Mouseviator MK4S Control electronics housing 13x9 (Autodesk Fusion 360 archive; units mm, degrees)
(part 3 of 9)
sketch "Side locks" plane through (100.9644, 0, 0) normal (1, 0, 0) x axis (0, 1, 0)
  line L1 (61.9172, 74.95) -> (61.9172, 5.05)
  line L2 (-67.9414, 74.95) -> (61.9172, 74.95)
  line L3 (-67.9414, 5.05) -> (-67.9414, 74.95)
  line L4 (61.9172, 5.05) -> (-67.9414, 5.05)
  line L5 (-3.0121, 22.271) -> (-3.0121, 127.629)
  line L6 (25.9775, 40) -> (-161.8603, 40)
  line L7 (-67.9414, 64.95) -> (-67.9414, 74.95)
  line L8 (-61.9414, 74.95) -> (-67.9414, 74.95)
  line L9 (-61.9414, 59.95) -> (-61.9414, 74.95)
  line L10 (-67.9414, 64.95) -> (-61.9414, 59.95)
  line L11 (-67.9471, 64.9636) -> (-73.8914, 60.0101)
  line L12 (-73.8914, 60.0101) -> (-73.8914, 74.9101)
  line L13 (-67.9414, 64.9636) -> (-67.9471, 64.9636)
  line L14 (-67.9414, 74.9101) -> (-73.8914, 74.9101)
  line L15 (-67.9414, 5.0899) -> (-73.8914, 5.0899)
  line L16 (-73.8914, 19.9899) -> (-73.8914, 5.0899)
  line L17 (-67.9471, 15.0364) -> (-73.8914, 19.9899)
  line L18 (-67.9414, 15.0364) -> (-67.9471, 15.0364)
  line L19 (-67.9414, 15.05) -> (-67.9414, 5.05)
  line L20 (-61.9414, 5.05) -> (-67.9414, 5.05)
  line L21 (-61.9414, 20.05) -> (-61.9414, 5.05)
  line L22 (-67.9414, 15.05) -> (-61.9414, 20.05)
  line L23 (61.9172, 64.95) -> (61.9172, 74.95)
  line L24 (55.9172, 74.95) -> (61.9172, 74.95)
  line L25 (55.9172, 59.95) -> (55.9172, 74.95)
  line L26 (61.9172, 64.95) -> (55.9172, 59.95)
  line L27 (61.9172, 74.9101) -> (67.8672, 74.9101)
  line L28 (67.8672, 60.0101) -> (67.8672, 74.9101)
  line L29 (61.9172, 64.9636) -> (61.9229, 64.9636)
  line L30 (61.9229, 64.9636) -> (67.8672, 60.0101)
  line L31 (61.9172, 5.0899) -> (67.8672, 5.0899)
  line L32 (67.8672, 19.9899) -> (67.8672, 5.0899)
  line L33 (61.9172, 15.0364) -> (61.9229, 15.0364)
  line L34 (61.9229, 15.0364) -> (67.8672, 19.9899)
  line L35 (61.9172, 15.05) -> (61.9172, 5.05)
  line L36 (55.9172, 5.05) -> (61.9172, 5.05)
  line L37 (55.9172, 20.05) -> (55.9172, 5.05)
  line L38 (61.9172, 15.05) -> (55.9172, 20.05)
  point P17 (-67.9414, 64.9636)
  point P18 (-67.9414, 74.9101)
  point P10 (-67.9414, 74.95)
  point P24 (-67.9414, 5.05)
  point P11 (-67.9414, 64.95)
  point P25 (-67.9414, 15.05)
  point P12 (-61.9414, 74.95)
  point P26 (-61.9414, 5.05)
  point P13 (-61.9414, 59.95)
  point P27 (-61.9414, 20.05)
  point P14 (-67.9471, 64.9636)
  point P22 (-67.9471, 15.0364)
  point P15 (-73.8914, 60.0101)
  point P21 (-73.8914, 19.9899)
  point P16 (-73.8914, 74.9101)
  point P19 (-73.8914, 5.0899)
  point P23 (-67.9414, 15.0364)
  point P20 (-67.9414, 5.0899)
  point P28 (61.9172, 74.95)
  point P29 (61.9172, 64.95)
  point P30 (55.9172, 74.95)
  point P31 (55.9172, 59.95)
  point P35 (61.9229, 64.9636)
  point P34 (67.8672, 60.0101)
  point P32 (67.8672, 74.9101)
  point P36 (61.9172, 64.9636)
  point P33 (61.9172, 74.9101)
  point P37 (67.8672, 5.0899)
  point P38 (61.9172, 5.0899)
  point P39 (67.8672, 19.9899)
  point P40 (61.9229, 15.0364)
  point P41 (61.9172, 15.0364)
  point P42 (61.9172, 5.05)
  point P43 (61.9172, 15.05)
  point P44 (55.9172, 5.05)
  point P45 (55.9172, 20.05)
  vertical L5
  perpendicular L1 L6
  coincident L7 P17
  horizontal L14
  coincident L3 P18
  symmetric L6 P10 P24
  symmetric L6 P11 P25
  symmetric L6 P12 P26
  symmetric L6 P13 P27
  symmetric L6 P14 P22
  symmetric L6 P15 P21
  symmetric L6 P16 P19
  symmetric L6 P17 P23
  symmetric L6 P18 P20
  midpoint L2 L5
  midpoint L3 L6
  symmetric L5 P10 P28
  symmetric L5 P11 P29
  symmetric L5 P12 P30
  symmetric L5 P13 P31
  symmetric L5 P14 P35
  symmetric L5 P15 P34
  symmetric L5 P16 P32
  symmetric L5 P17 P36
  symmetric L5 P18 P33
  symmetric L5 P19 P37
  symmetric L5 P20 P38
  symmetric L5 P21 P39
  symmetric L5 P22 P40
  symmetric L5 P23 P41
  symmetric L5 P24 P42
  symmetric L5 P25 P43
  symmetric L5 P26 P44
  symmetric L5 P27 P45
  dimension "d315" distance P12 P13 = 15 (= "join_width2")
  dimension "d316" distance P10 P11 = 10 (= "join_width1")
  dimension "d317" distance P10 P12 = 6 (= "join_depth * 2")
  dimension "d320" distance P16 P18 = 5.95 (= "join_depth * 2 - wall_clearance")
  dimension "d321" distance P15 P16 = 14.9 (= "join_width2 - 2 * wall_clearance")
sketch "wall_base" plane through (0, 0, 5) normal (0, 0, 1) x axis (-1, 0, 0)
  line L1 (-98.9644, -53.9879) -> (-98.9644, -59.9879)
  line L2 (-92.9644, -53.9879) -> (-98.9644, -53.9879)
  line L3 (-92.9644, -59.9879) -> (-92.9644, -53.9879)
  line L4 (-98.9644, -59.9879) -> (-92.9644, -59.9879)
  line L5 (-12.9644, 60.0121) -> (-12.9644, 66.0121)
  line L6 (-18.9644, 60.0121) -> (-12.9644, 60.0121)
  line L7 (-18.9644, 66.0121) -> (-18.9644, 60.0121)
  line L8 (-12.9644, 66.0121) -> (-18.9644, 66.0121)
  line L9 (-45.9644, -51.9879) -> (-20.9644, -51.9879)
  line L10 (-40.9644, -54.9879) -> (-45.9644, -51.9879)
  line L11 (-70.9644, -54.9879) -> (-40.9644, -54.9879)
  line L12 (-65.9644, -51.9879) -> (-70.9644, -54.9879)
  line L13 (-90.9644, -51.9879) -> (-65.9644, -51.9879)
  line L14 (-90.9644, -6.9879) -> (-90.9644, -51.9879)
  line L15 (-93.9644, -11.9879) -> (-90.9644, -6.9879)
  line L16 (-93.9644, 18.0121) -> (-93.9644, -11.9879)
  line L17 (-90.9644, 13.0121) -> (-93.9644, 18.0121)
  line L18 (-90.9644, 58.0121) -> (-90.9644, 13.0121)
  line L19 (-65.9644, 58.0121) -> (-90.9644, 58.0121)
  line L20 (-70.9644, 61.0121) -> (-65.9644, 58.0121)
  line L21 (-40.9644, 61.0121) -> (-70.9644, 61.0121)
  line L22 (-45.9644, 58.0121) -> (-40.9644, 61.0121)
  line L23 (-20.9644, 58.0121) -> (-45.9644, 58.0121)
  line L24 (-20.9644, 13.0121) -> (-20.9644, 58.0121)
  line L25 (-17.9644, 18.0121) -> (-20.9644, 13.0121)
  line L26 (-17.9644, -11.9879) -> (-17.9644, 18.0121)
  line L27 (-20.9644, -6.9879) -> (-17.9644, -11.9879)
  line L28 (-20.9644, -51.9879) -> (-20.9644, -6.9879)
  line L29 (-12.9644, -53.9879) -> (-18.9644, -53.9879)
  line L30 (-12.9644, -59.9879) -> (-12.9644, -53.9879)
  line L31 (-18.9644, -59.9879) -> (-12.9644, -59.9879)
  line L32 (-18.9644, -53.9879) -> (-18.9644, -59.9879)
  line L33 (-98.9644, 60.0121) -> (-92.9644, 60.0121)
  line L34 (-98.9644, 66.0121) -> (-98.9644, 60.0121)
  line L35 (-92.9644, 66.0121) -> (-98.9644, 66.0121)
  line L36 (-92.9644, 60.0121) -> (-92.9644, 66.0121)
  line L37 (-10.9644, -6.9879) -> (-10.9644, -61.9879)
  line L38 (-13.9644, -11.9879) -> (-10.9644, -6.9879)
  line L39 (-13.9644, 18.0121) -> (-13.9644, -11.9879)
  line L40 (-10.9644, 13.0121) -> (-13.9644, 18.0121)
  line L41 (-10.9644, 68.0121) -> (-10.9644, 13.0121)
  line L42 (-45.9644, 68.0121) -> (-10.9644, 68.0121)
  line L43 (-40.9644, 65.0121) -> (-45.9644, 68.0121)
  line L44 (-70.9644, 65.0121) -> (-40.9644, 65.0121)
  line L45 (-65.9644, 68.0121) -> (-70.9644, 65.0121)
  line L46 (-100.9644, 68.0121) -> (-65.9644, 68.0121)
  line L47 (-100.9644, 13.0121) -> (-100.9644, 68.0121)
  line L48 (-97.9644, 18.0121) -> (-100.9644, 13.0121)
  line L49 (-97.9644, -11.9879) -> (-97.9644, 18.0121)
  line L50 (-100.9644, -6.9879) -> (-97.9644, -11.9879)
  line L51 (-100.9644, -61.9879) -> (-100.9644, -6.9879)
  line L52 (-65.9644, -61.9879) -> (-100.9644, -61.9879)
  line L53 (-70.9644, -58.9879) -> (-65.9644, -61.9879)
  line L54 (-40.9644, -58.9879) -> (-70.9644, -58.9879)
  line L55 (-45.9644, -61.9879) -> (-40.9644, -58.9879)
  line L56 (-10.9644, -61.9879) -> (-45.9644, -61.9879)
  line L57 (-100.9644, -61.9879) -> (-100.9644, 68.0121)
  line L58 (-100.9644, -61.9172) -> (-100.0144, -60.9672)
  line L59 (-100.0144, -52.9379) -> (-100.0144, -60.9672)
  line L60 (-99.0144, -52.9379) -> (-100.0144, -52.9379)
  line L61 (-99.0144, 58.9451) -> (-99.0144, -52.9379)
  line L62 (-100.0144, 58.9621) -> (-99.0144, 58.9451)
  line L63 (-100.0144, 66.9914) -> (-100.0144, 58.9621)
  line L64 (-100.9644, 67.9414) -> (-100.0144, 66.9914)
  line L65 (-99.9644, -52.9879) -> (-99.9644, -60.9879)
  line L66 (-98.9644, -52.9879) -> (-99.9644, -52.9879)
  line L67 (-98.9644, 58.9942) -> (-98.9644, -52.9879)
  line L68 (-99.9644, 59.0113) -> (-98.9644, 58.9942)
  line L69 (-99.9644, 67.0121) -> (-99.9644, 59.0113)
  line L70 (-100.9644, -61.9879) -> (-99.9644, -60.9879)
  line L71 (-100.9644, 68.0121) -> (-99.9644, 67.0121)
  circle C1 centre (-24.4644, 61.5121) radius 1.7
  circle C2 centre (-93.9644, 54.5121) radius 1.7
  circle C3 centre (-87.4644, -55.4879) radius 1.7
  circle C4 centre (-17.4644, -48.4879) radius 1.7
  circle C5 centre (-24.4644, -55.4879) radius 1.7
  circle C6 centre (-93.9644, -48.4879) radius 1.7
  circle C7 centre (-87.4644, 61.5121) radius 1.7
  circle C8 centre (-17.4644, 54.5121) radius 1.7
  point P69 (-100.9644, 68.0121)
  point P74 (-100.9644, 68.0121)
  point P68 (-100.9644, -61.9879)
  point P75 (-100.9644, -61.9879)
  point P82 (-100.9644, 67.9414)
  point P83 (-100.9644, -61.9172)
  point P90 (-100.9644, -61.9879)
  point P91 (-100.9644, 68.0121)
  point P77 (-100.0144, -52.9379)
  point P80 (-100.0144, 58.9621)
  coincident P69 P74
  coincident P68 P75
  coincident L47 P82
  coincident L51 P83
  coincident P68 P90
  parallel L58 L70
  coincident P69 P91
  dimension "d147_1" distance L57 L63 = 0.95 (= "side_wall_thick1")
  dimension "d148_1" distance L57 L61 = 1.95 (= "side_wall_thick2")
  dimension "d151_1" distance L57 L59 = 0.95 (= "side_wall_thick1")
  dimension "d157_1" distance L64 L71 = 0.05 (= "wall_clearance")
  dimension "d158_1" distance L58 L70 = 0.05 (= "wall_clearance")
  dimension "wall_rorner_angle_1" angle L46 L71 = 45
  dimension "d165_1" angle L52 L70 = 45 (= "wall_rorner_angle_1")
  dimension "d170_1" distance P75 P77 = 9.05
  dimension "d175_1" distance P74 P80 = 9.05 (= "side_wall_col_length")
extrude "Extrude1" new body sketch "wall_base" profile of L47 L48 L50 L51 L57 L58 L59 L62 L61 L60 L63 L64 blind 69.9 (= "column_height - ( 2 * wall_clearance )") named "d128_1" from offset 0.05 (= "wall_clearance") named "d127_1" bodies "side cover"
sketch "Sketch3" plane through (100.9644, 0, 0) normal (1, 0, 0) x axis (0, 1, 0)
  line L1 (61.9172, 5.05) -> (-67.9414, 5.05)
  line L2 (61.9172, 74.95) -> (61.9172, 5.05)
  line L3 (-67.9414, 74.95) -> (61.9172, 74.95)
  line L4 (-67.9414, 5.05) -> (-67.9414, 74.95)
  line L5 (61.9172, 74.95) -> (-67.9414, 74.95)
  line L6 (61.9172, 74.95) -> (61.9172, 5.05)
  line L7 (61.9172, 5.05) -> (-67.9414, 5.05)
  line L8 (-67.9414, 74.95) -> (-67.9414, 5.05)
  line L9 (-57.9414, 64.95) -> (51.9172, 64.95)
  line L10 (-57.9414, 15.05) -> (-57.9414, 64.95)
  line L11 (51.9172, 15.05) -> (-57.9414, 15.05)
  line L12 (51.9172, 64.95) -> (51.9172, 15.05)
  circle C1 centre (-62.995, 60) radius 1.7
  circle C2 centre (-62.995, 20) radius 1.7
  circle C3 centre (56.9879, 60) radius 1.7
  circle C4 centre (56.9879, 20) radius 1.7
sketch "Side locks" plane through (100.9644, 0, 0) normal (1, 0, 0) x axis (0, 1, 0)
  line L1 (61.9172, 74.95) -> (61.9172, 5.05)
  line L2 (-67.9414, 74.95) -> (61.9172, 74.95)
  line L3 (-67.9414, 5.05) -> (-67.9414, 74.95)
  line L4 (61.9172, 5.05) -> (-67.9414, 5.05)
  line L5 (-3.0121, 22.271) -> (-3.0121, 127.629)
  line L6 (25.9775, 40) -> (-161.8603, 40)
  line L7 (-67.9414, 64.95) -> (-67.9414, 74.95)
  line L8 (-61.9414, 74.95) -> (-67.9414, 74.95)
  line L9 (-61.9414, 59.95) -> (-61.9414, 74.95)
  line L10 (-67.9414, 64.95) -> (-61.9414, 59.95)
  line L11 (-67.9471, 64.9636) -> (-73.8914, 60.0101)
  line L12 (-73.8914, 60.0101) -> (-73.8914, 74.9101)
  line L13 (-67.9414, 64.9636) -> (-67.9471, 64.9636)
  line L14 (-67.9414, 74.9101) -> (-73.8914, 74.9101)
  line L15 (-67.9414, 5.0899) -> (-73.8914, 5.0899)
  line L16 (-73.8914, 19.9899) -> (-73.8914, 5.0899)
  line L17 (-67.9471, 15.0364) -> (-73.8914, 19.9899)
  line L18 (-67.9414, 15.0364) -> (-67.9471, 15.0364)
  line L19 (-67.9414, 15.05) -> (-67.9414, 5.05)
  line L20 (-61.9414, 5.05) -> (-67.9414, 5.05)
  line L21 (-61.9414, 20.05) -> (-61.9414, 5.05)
  line L22 (-67.9414, 15.05) -> (-61.9414, 20.05)
  line L23 (61.9172, 64.95) -> (61.9172, 74.95)
  line L24 (55.9172, 74.95) -> (61.9172, 74.95)
  line L25 (55.9172, 59.95) -> (55.9172, 74.95)
  line L26 (61.9172, 64.95) -> (55.9172, 59.95)
  line L27 (61.9172, 74.9101) -> (67.8672, 74.9101)
  line L28 (67.8672, 60.0101) -> (67.8672, 74.9101)
  line L29 (61.9172, 64.9636) -> (61.9229, 64.9636)
  line L30 (61.9229, 64.9636) -> (67.8672, 60.0101)
  line L31 (61.9172, 5.0899) -> (67.8672, 5.0899)
  line L32 (67.8672, 19.9899) -> (67.8672, 5.0899)
  line L33 (61.9172, 15.0364) -> (61.9229, 15.0364)
  line L34 (61.9229, 15.0364) -> (67.8672, 19.9899)
  line L35 (61.9172, 15.05) -> (61.9172, 5.05)
  line L36 (55.9172, 5.05) -> (61.9172, 5.05)
  line L37 (55.9172, 20.05) -> (55.9172, 5.05)
  line L38 (61.9172, 15.05) -> (55.9172, 20.05)
  point P17 (-67.9414, 64.9636)
  point P18 (-67.9414, 74.9101)
  point P10 (-67.9414, 74.95)
  point P24 (-67.9414, 5.05)
  point P11 (-67.9414, 64.95)
  point P25 (-67.9414, 15.05)
  point P12 (-61.9414, 74.95)
  point P26 (-61.9414, 5.05)
  point P13 (-61.9414, 59.95)
  point P27 (-61.9414, 20.05)
  point P14 (-67.9471, 64.9636)
  point P22 (-67.9471, 15.0364)
  point P15 (-73.8914, 60.0101)
  point P21 (-73.8914, 19.9899)
  point P16 (-73.8914, 74.9101)
  point P19 (-73.8914, 5.0899)
  point P23 (-67.9414, 15.0364)
  point P20 (-67.9414, 5.0899)
  point P28 (61.9172, 74.95)
  point P29 (61.9172, 64.95)
  point P30 (55.9172, 74.95)
  point P31 (55.9172, 59.95)
  point P35 (61.9229, 64.9636)
  point P34 (67.8672, 60.0101)
  point P32 (67.8672, 74.9101)
  point P36 (61.9172, 64.9636)
  point P33 (61.9172, 74.9101)
  point P37 (67.8672, 5.0899)
  point P38 (61.9172, 5.0899)
  point P39 (67.8672, 19.9899)
  point P40 (61.9229, 15.0364)
  point P41 (61.9172, 15.0364)
  point P42 (61.9172, 5.05)
  point P43 (61.9172, 15.05)
  point P44 (55.9172, 5.05)
  point P45 (55.9172, 20.05)
  vertical L5
  perpendicular L1 L6
  coincident L7 P17
  horizontal L14
  coincident L3 P18
  symmetric L6 P10 P24
  symmetric L6 P11 P25
  symmetric L6 P12 P26
  symmetric L6 P13 P27
  symmetric L6 P14 P22
  symmetric L6 P15 P21
  symmetric L6 P16 P19
  symmetric L6 P17 P23
  symmetric L6 P18 P20
  midpoint L2 L5
  midpoint L3 L6
  symmetric L5 P10 P28
  symmetric L5 P11 P29
  symmetric L5 P12 P30
  symmetric L5 P13 P31
  symmetric L5 P14 P35
  symmetric L5 P15 P34
  symmetric L5 P16 P32
  symmetric L5 P17 P36
  symmetric L5 P18 P33
  symmetric L5 P19 P37
  symmetric L5 P20 P38
  symmetric L5 P21 P39
  symmetric L5 P22 P40
  symmetric L5 P23 P41
  symmetric L5 P24 P42
  symmetric L5 P25 P43
  symmetric L5 P26 P44
  symmetric L5 P27 P45
  dimension "d315_1" distance P12 P13 = 15 (= "join_width2")
  dimension "d316_1" distance P10 P11 = 10 (= "join_width1")
  dimension "d317_1" distance P10 P12 = 6 (= "join_depth * 2")
  dimension "d320_1" distance P16 P18 = 5.95 (= "join_depth * 2 - wall_clearance")
  dimension "d321_1" distance P15 P16 = 14.9 (= "join_width2 - 2 * wall_clearance")
position "Position9"
extrude "Extrude3" cut sketch "Side locks" profile of L1 L2 L3 L4 L7 L8 L9 L10 L19 L20 L21 L22 L23 L24 L25 L26 L35 L36 L37 L38 against normal blind 5
sketch "wall_base" plane through (0, 0, 5) normal (0, 0, 1) x axis (-1, 0, 0)
  line L1 (-98.9644, -53.9879) -> (-98.9644, -59.9879)
  line L2 (-92.9644, -53.9879) -> (-98.9644, -53.9879)
  line L3 (-92.9644, -59.9879) -> (-92.9644, -53.9879)
  line L4 (-98.9644, -59.9879) -> (-92.9644, -59.9879)
  line L5 (-12.9644, 60.0121) -> (-12.9644, 66.0121)
  line L6 (-18.9644, 60.0121) -> (-12.9644, 60.0121)
  line L7 (-18.9644, 66.0121) -> (-18.9644, 60.0121)
  line L8 (-12.9644, 66.0121) -> (-18.9644, 66.0121)
  line L9 (-45.9644, -51.9879) -> (-20.9644, -51.9879)
  line L10 (-40.9644, -54.9879) -> (-45.9644, -51.9879)
  line L11 (-70.9644, -54.9879) -> (-40.9644, -54.9879)
  line L12 (-65.9644, -51.9879) -> (-70.9644, -54.9879)
  line L13 (-90.9644, -51.9879) -> (-65.9644, -51.9879)
  line L14 (-90.9644, -6.9879) -> (-90.9644, -51.9879)
  line L15 (-93.9644, -11.9879) -> (-90.9644, -6.9879)
  line L16 (-93.9644, 18.0121) -> (-93.9644, -11.9879)
  line L17 (-90.9644, 13.0121) -> (-93.9644, 18.0121)
  line L18 (-90.9644, 58.0121) -> (-90.9644, 13.0121)
  line L19 (-65.9644, 58.0121) -> (-90.9644, 58.0121)
  line L20 (-70.9644, 61.0121) -> (-65.9644, 58.0121)
  line L21 (-40.9644, 61.0121) -> (-70.9644, 61.0121)
  line L22 (-45.9644, 58.0121) -> (-40.9644, 61.0121)
  line L23 (-20.9644, 58.0121) -> (-45.9644, 58.0121)
  line L24 (-20.9644, 13.0121) -> (-20.9644, 58.0121)
  line L25 (-17.9644, 18.0121) -> (-20.9644, 13.0121)
  line L26 (-17.9644, -11.9879) -> (-17.9644, 18.0121)
  line L27 (-20.9644, -6.9879) -> (-17.9644, -11.9879)
  line L28 (-20.9644, -51.9879) -> (-20.9644, -6.9879)
  line L29 (-12.9644, -53.9879) -> (-18.9644, -53.9879)
  line L30 (-12.9644, -59.9879) -> (-12.9644, -53.9879)
  line L31 (-18.9644, -59.9879) -> (-12.9644, -59.9879)
  line L32 (-18.9644, -53.9879) -> (-18.9644, -59.9879)
  line L33 (-98.9644, 60.0121) -> (-92.9644, 60.0121)
  line L34 (-98.9644, 66.0121) -> (-98.9644, 60.0121)
  line L35 (-92.9644, 66.0121) -> (-98.9644, 66.0121)
  line L36 (-92.9644, 60.0121) -> (-92.9644, 66.0121)
  line L37 (-10.9644, -6.9879) -> (-10.9644, -61.9879)
  line L38 (-13.9644, -11.9879) -> (-10.9644, -6.9879)
  line L39 (-13.9644, 18.0121) -> (-13.9644, -11.9879)
  line L40 (-10.9644, 13.0121) -> (-13.9644, 18.0121)
  line L41 (-10.9644, 68.0121) -> (-10.9644, 13.0121)
  line L42 (-45.9644, 68.0121) -> (-10.9644, 68.0121)
  line L43 (-40.9644, 65.0121) -> (-45.9644, 68.0121)
  line L44 (-70.9644, 65.0121) -> (-40.9644, 65.0121)
  line L45 (-65.9644, 68.0121) -> (-70.9644, 65.0121)
  line L46 (-100.9644, 68.0121) -> (-65.9644, 68.0121)
  line L47 (-100.9644, 13.0121) -> (-100.9644, 68.0121)
  line L48 (-97.9644, 18.0121) -> (-100.9644, 13.0121)
  line L49 (-97.9644, -11.9879) -> (-97.9644, 18.0121)
  line L50 (-100.9644, -6.9879) -> (-97.9644, -11.9879)
  line L51 (-100.9644, -61.9879) -> (-100.9644, -6.9879)
  line L52 (-65.9644, -61.9879) -> (-100.9644, -61.9879)
  line L53 (-70.9644, -58.9879) -> (-65.9644, -61.9879)
  line L54 (-40.9644, -58.9879) -> (-70.9644, -58.9879)
  line L55 (-45.9644, -61.9879) -> (-40.9644, -58.9879)
  line L56 (-10.9644, -61.9879) -> (-45.9644, -61.9879)
  line L57 (-100.9644, -61.9879) -> (-100.9644, 68.0121)
  line L58 (-100.9644, -61.9172) -> (-100.0144, -60.9672)
  line L59 (-100.0144, -52.9379) -> (-100.0144, -60.9672)
  line L60 (-99.0144, -52.9379) -> (-100.0144, -52.9379)
  line L61 (-99.0144, 58.9451) -> (-99.0144, -52.9379)
  line L62 (-100.0144, 58.9621) -> (-99.0144, 58.9451)
  line L63 (-100.0144, 66.9914) -> (-100.0144, 58.9621)
  line L64 (-100.9644, 67.9414) -> (-100.0144, 66.9914)
  line L65 (-99.9644, -52.9879) -> (-99.9644, -60.9879)
  line L66 (-98.9644, -52.9879) -> (-99.9644, -52.9879)
  line L67 (-98.9644, 58.9942) -> (-98.9644, -52.9879)
  line L68 (-99.9644, 59.0113) -> (-98.9644, 58.9942)
  line L69 (-99.9644, 67.0121) -> (-99.9644, 59.0113)
  line L70 (-100.9644, -61.9879) -> (-99.9644, -60.9879)
  line L71 (-100.9644, 68.0121) -> (-99.9644, 67.0121)
  circle C1 centre (-24.4644, 61.5121) radius 1.7
  circle C2 centre (-93.9644, 54.5121) radius 1.7
  circle C3 centre (-87.4644, -55.4879) radius 1.7
  circle C4 centre (-17.4644, -48.4879) radius 1.7
  circle C5 centre (-24.4644, -55.4879) radius 1.7
  circle C6 centre (-93.9644, -48.4879) radius 1.7
  circle C7 centre (-87.4644, 61.5121) radius 1.7
  circle C8 centre (-17.4644, 54.5121) radius 1.7
  point P69 (-100.9644, 68.0121)
  point P74 (-100.9644, 68.0121)
  point P68 (-100.9644, -61.9879)
  point P75 (-100.9644, -61.9879)
  point P82 (-100.9644, 67.9414)
  point P83 (-100.9644, -61.9172)
  point P90 (-100.9644, -61.9879)
  point P91 (-100.9644, 68.0121)
  point P77 (-100.0144, -52.9379)
  point P80 (-100.0144, 58.9621)
  coincident P69 P74
  coincident P68 P75
  coincident L47 P82
  coincident L51 P83
  coincident P68 P90
  parallel L58 L70
  coincident P69 P91
  dimension "d147_2" distance L57 L63 = 0.95 (= "side_wall_thick1")
  dimension "d148_2" distance L57 L61 = 1.95 (= "side_wall_thick2")
  dimension "d151_2" distance L57 L59 = 0.95 (= "side_wall_thick1")
  dimension "d157_2" distance L64 L71 = 0.05 (= "wall_clearance")
  dimension "d158_2" distance L58 L70 = 0.05 (= "wall_clearance")
  dimension "wall_rorner_angle_2" angle L46 L71 = 45
  dimension "d165_2" angle L52 L70 = 45 (= "wall_rorner_angle_2")
  dimension "d170_2" distance P75 P77 = 9.05
  dimension "d175_2" distance P74 P80 = 9.05 (= "side_wall_col_length")
extrude "Extrude1" new body sketch "wall_base" profile of L47 L48 L50 L51 L57 L58 L59 L62 L61 L60 L63 L64 blind 69.9 (= "column_height - ( 2 * wall_clearance )") named "d128_2" from offset 0.05 (= "wall_clearance") named "d127_2" bodies "side cover"
sketch "Sketch3" plane through (100.9644, 0, 0) normal (1, 0, 0) x axis (0, 1, 0)
  line L1 (61.9172, 5.05) -> (-67.9414, 5.05)
  line L2 (61.9172, 74.95) -> (61.9172, 5.05)
  line L3 (-67.9414, 74.95) -> (61.9172, 74.95)
  line L4 (-67.9414, 5.05) -> (-67.9414, 74.95)
  line L5 (61.9172, 74.95) -> (-67.9414, 74.95)
  line L6 (61.9172, 74.95) -> (61.9172, 5.05)
  line L7 (61.9172, 5.05) -> (-67.9414, 5.05)
  line L8 (-67.9414, 74.95) -> (-67.9414, 5.05)
  line L9 (-57.9414, 64.95) -> (51.9172, 64.95)
  line L10 (-57.9414, 15.05) -> (-57.9414, 64.95)
  line L11 (51.9172, 15.05) -> (-57.9414, 15.05)
  line L12 (51.9172, 64.95) -> (51.9172, 15.05)
  circle C1 centre (-62.995, 60) radius 1.7
  circle C2 centre (-62.995, 20) radius 1.7
  circle C3 centre (56.9879, 60) radius 1.7
  circle C4 centre (56.9879, 20) radius 1.7
hole "Hole1" HoleDepth 4 named "d134_1" HoleDiameter 3.4 named "d135_1" TipAngle 118 named "d136_1"
sketch "Side locks" plane through (100.9644, 0, 0) normal (1, 0, 0) x axis (0, 1, 0)
  line L1 (61.9172, 74.95) -> (61.9172, 5.05)
  line L2 (-67.9414, 74.95) -> (61.9172, 74.95)
  line L3 (-67.9414, 5.05) -> (-67.9414, 74.95)
  line L4 (61.9172, 5.05) -> (-67.9414, 5.05)
  line L5 (-3.0121, 22.271) -> (-3.0121, 127.629)
  line L6 (25.9775, 40) -> (-161.8603, 40)
  line L7 (-67.9414, 64.95) -> (-67.9414, 74.95)
  line L8 (-61.9414, 74.95) -> (-67.9414, 74.95)
  line L9 (-61.9414, 59.95) -> (-61.9414, 74.95)
  line L10 (-67.9414, 64.95) -> (-61.9414, 59.95)
  line L11 (-67.9471, 64.9636) -> (-73.8914, 60.0101)
  line L12 (-73.8914, 60.0101) -> (-73.8914, 74.9101)
  line L13 (-67.9414, 64.9636) -> (-67.9471, 64.9636)
  line L14 (-67.9414, 74.9101) -> (-73.8914, 74.9101)
  line L15 (-67.9414, 5.0899) -> (-73.8914, 5.0899)
  line L16 (-73.8914, 19.9899) -> (-73.8914, 5.0899)
  line L17 (-67.9471, 15.0364) -> (-73.8914, 19.9899)
  line L18 (-67.9414, 15.0364) -> (-67.9471, 15.0364)
  line L19 (-67.9414, 15.05) -> (-67.9414, 5.05)
  line L20 (-61.9414, 5.05) -> (-67.9414, 5.05)
  line L21 (-61.9414, 20.05) -> (-61.9414, 5.05)
  line L22 (-67.9414, 15.05) -> (-61.9414, 20.05)
  line L23 (61.9172, 64.95) -> (61.9172, 74.95)
  line L24 (55.9172, 74.95) -> (61.9172, 74.95)
  line L25 (55.9172, 59.95) -> (55.9172, 74.95)
  line L26 (61.9172, 64.95) -> (55.9172, 59.95)
  line L27 (61.9172, 74.9101) -> (67.8672, 74.9101)
  line L28 (67.8672, 60.0101) -> (67.8672, 74.9101)
  line L29 (61.9172, 64.9636) -> (61.9229, 64.9636)
  line L30 (61.9229, 64.9636) -> (67.8672, 60.0101)
  line L31 (61.9172, 5.0899) -> (67.8672, 5.0899)
  line L32 (67.8672, 19.9899) -> (67.8672, 5.0899)
  line L33 (61.9172, 15.0364) -> (61.9229, 15.0364)
  line L34 (61.9229, 15.0364) -> (67.8672, 19.9899)
  line L35 (61.9172, 15.05) -> (61.9172, 5.05)
  line L36 (55.9172, 5.05) -> (61.9172, 5.05)
  line L37 (55.9172, 20.05) -> (55.9172, 5.05)
  line L38 (61.9172, 15.05) -> (55.9172, 20.05)
  point P17 (-67.9414, 64.9636)
  point P18 (-67.9414, 74.9101)
  point P10 (-67.9414, 74.95)
  point P24 (-67.9414, 5.05)
  point P11 (-67.9414, 64.95)
  point P25 (-67.9414, 15.05)
  point P12 (-61.9414, 74.95)
  point P26 (-61.9414, 5.05)
  point P13 (-61.9414, 59.95)
  point P27 (-61.9414, 20.05)
  point P14 (-67.9471, 64.9636)
  point P22 (-67.9471, 15.0364)
  point P15 (-73.8914, 60.0101)
  point P21 (-73.8914, 19.9899)
  point P16 (-73.8914, 74.9101)
  point P19 (-73.8914, 5.0899)
  point P23 (-67.9414, 15.0364)
  point P20 (-67.9414, 5.0899)
  point P28 (61.9172, 74.95)
  point P29 (61.9172, 64.95)
  point P30 (55.9172, 74.95)
  point P31 (55.9172, 59.95)
  point P35 (61.9229, 64.9636)
  point P34 (67.8672, 60.0101)
  point P32 (67.8672, 74.9101)
  point P36 (61.9172, 64.9636)
  point P33 (61.9172, 74.9101)
  point P37 (67.8672, 5.0899)
  point P38 (61.9172, 5.0899)
  point P39 (67.8672, 19.9899)
  point P40 (61.9229, 15.0364)
  point P41 (61.9172, 15.0364)
  point P42 (61.9172, 5.05)
  point P43 (61.9172, 15.05)
  point P44 (55.9172, 5.05)
  point P45 (55.9172, 20.05)
  vertical L5
  perpendicular L1 L6
  coincident L7 P17
  horizontal L14
  coincident L3 P18
  symmetric L6 P10 P24
  symmetric L6 P11 P25
  symmetric L6 P12 P26
  symmetric L6 P13 P27
  symmetric L6 P14 P22
  symmetric L6 P15 P21
  symmetric L6 P16 P19
  symmetric L6 P17 P23
  symmetric L6 P18 P20
  midpoint L2 L5
  midpoint L3 L6
  symmetric L5 P10 P28
  symmetric L5 P11 P29
  symmetric L5 P12 P30
  symmetric L5 P13 P31
  symmetric L5 P14 P35
  symmetric L5 P15 P34
  symmetric L5 P16 P32
  symmetric L5 P17 P36
  symmetric L5 P18 P33
  symmetric L5 P19 P37
  symmetric L5 P20 P38
  symmetric L5 P21 P39
  symmetric L5 P22 P40
  symmetric L5 P23 P41
  symmetric L5 P24 P42
  symmetric L5 P25 P43
  symmetric L5 P26 P44
  symmetric L5 P27 P45
  dimension "d315_2" distance P12 P13 = 15 (= "join_width2")
  dimension "d316_2" distance P10 P11 = 10 (= "join_width1")
  dimension "d317_2" distance P10 P12 = 6 (= "join_depth * 2")
  dimension "d320_2" distance P16 P18 = 5.95 (= "join_depth * 2 - wall_clearance")
  dimension "d321_2" distance P15 P16 = 14.9 (= "join_width2 - 2 * wall_clearance")
position "Position10"
extrude "Extrude3" cut sketch "Side locks" profile of L2 L3 L4 L7 L8 L9 L10 L19 L20 L21 L22 against normal blind 5
sketch "wall_base" plane through (0, 0, 5) normal (0, 0, 1) x axis (-1, 0, 0)
  line L1 (-98.9644, -53.9879) -> (-98.9644, -59.9879)
  line L2 (-92.9644, -53.9879) -> (-98.9644, -53.9879)
  line L3 (-92.9644, -59.9879) -> (-92.9644, -53.9879)
  line L4 (-98.9644, -59.9879) -> (-92.9644, -59.9879)
  line L5 (-12.9644, 60.0121) -> (-12.9644, 66.0121)
  line L6 (-18.9644, 60.0121) -> (-12.9644, 60.0121)
  line L7 (-18.9644, 66.0121) -> (-18.9644, 60.0121)
  line L8 (-12.9644, 66.0121) -> (-18.9644, 66.0121)
  line L9 (-45.9644, -51.9879) -> (-20.9644, -51.9879)
  line L10 (-40.9644, -54.9879) -> (-45.9644, -51.9879)
  line L11 (-70.9644, -54.9879) -> (-40.9644, -54.9879)
  line L12 (-65.9644, -51.9879) -> (-70.9644, -54.9879)
  line L13 (-90.9644, -51.9879) -> (-65.9644, -51.9879)
  line L14 (-90.9644, -6.9879) -> (-90.9644, -51.9879)
  line L15 (-93.9644, -11.9879) -> (-90.9644, -6.9879)
  line L16 (-93.9644, 18.0121) -> (-93.9644, -11.9879)
  line L17 (-90.9644, 13.0121) -> (-93.9644, 18.0121)
  line L18 (-90.9644, 58.0121) -> (-90.9644, 13.0121)
  line L19 (-65.9644, 58.0121) -> (-90.9644, 58.0121)
  line L20 (-70.9644, 61.0121) -> (-65.9644, 58.0121)
  line L21 (-40.9644, 61.0121) -> (-70.9644, 61.0121)
  line L22 (-45.9644, 58.0121) -> (-40.9644, 61.0121)
  line L23 (-20.9644, 58.0121) -> (-45.9644, 58.0121)
  line L24 (-20.9644, 13.0121) -> (-20.9644, 58.0121)
  line L25 (-17.9644, 18.0121) -> (-20.9644, 13.0121)
  line L26 (-17.9644, -11.9879) -> (-17.9644, 18.0121)
  line L27 (-20.9644, -6.9879) -> (-17.9644, -11.9879)
  line L28 (-20.9644, -51.9879) -> (-20.9644, -6.9879)
  line L29 (-12.9644, -53.9879) -> (-18.9644, -53.9879)
  line L30 (-12.9644, -59.9879) -> (-12.9644, -53.9879)
  line L31 (-18.9644, -59.9879) -> (-12.9644, -59.9879)
  line L32 (-18.9644, -53.9879) -> (-18.9644, -59.9879)
  line L33 (-98.9644, 60.0121) -> (-92.9644, 60.0121)
  line L34 (-98.9644, 66.0121) -> (-98.9644, 60.0121)
  line L35 (-92.9644, 66.0121) -> (-98.9644, 66.0121)
  line L36 (-92.9644, 60.0121) -> (-92.9644, 66.0121)
  line L37 (-10.9644, -6.9879) -> (-10.9644, -61.9879)
  line L38 (-13.9644, -11.9879) -> (-10.9644, -6.9879)
  line L39 (-13.9644, 18.0121) -> (-13.9644, -11.9879)
  line L40 (-10.9644, 13.0121) -> (-13.9644, 18.0121)
  line L41 (-10.9644, 68.0121) -> (-10.9644, 13.0121)
  line L42 (-45.9644, 68.0121) -> (-10.9644, 68.0121)
  line L43 (-40.9644, 65.0121) -> (-45.9644, 68.0121)
  line L44 (-70.9644, 65.0121) -> (-40.9644, 65.0121)
  line L45 (-65.9644, 68.0121) -> (-70.9644, 65.0121)
  line L46 (-100.9644, 68.0121) -> (-65.9644, 68.0121)
  line L47 (-100.9644, 13.0121) -> (-100.9644, 68.0121)
  line L48 (-97.9644, 18.0121) -> (-100.9644, 13.0121)
  line L49 (-97.9644, -11.9879) -> (-97.9644, 18.0121)
  line L50 (-100.9644, -6.9879) -> (-97.9644, -11.9879)
  line L51 (-100.9644, -61.9879) -> (-100.9644, -6.9879)
  line L52 (-65.9644, -61.9879) -> (-100.9644, -61.9879)
  line L53 (-70.9644, -58.9879) -> (-65.9644, -61.9879)
  line L54 (-40.9644, -58.9879) -> (-70.9644, -58.9879)
  line L55 (-45.9644, -61.9879) -> (-40.9644, -58.9879)
  line L56 (-10.9644, -61.9879) -> (-45.9644, -61.9879)
  line L57 (-100.9644, -61.9879) -> (-100.9644, 68.0121)
  line L58 (-100.9644, -61.9172) -> (-100.0144, -60.9672)
  line L59 (-100.0144, -52.9379) -> (-100.0144, -60.9672)
  line L60 (-99.0144, -52.9379) -> (-100.0144, -52.9379)
  line L61 (-99.0144, 58.9451) -> (-99.0144, -52.9379)
  line L62 (-100.0144, 58.9621) -> (-99.0144, 58.9451)
  line L63 (-100.0144, 66.9914) -> (-100.0144, 58.9621)
  line L64 (-100.9644, 67.9414) -> (-100.0144, 66.9914)
  line L65 (-99.9644, -52.9879) -> (-99.9644, -60.9879)
  line L66 (-98.9644, -52.9879) -> (-99.9644, -52.9879)
  line L67 (-98.9644, 58.9942) -> (-98.9644, -52.9879)
  line L68 (-99.9644, 59.0113) -> (-98.9644, 58.9942)
  line L69 (-99.9644, 67.0121) -> (-99.9644, 59.0113)
  line L70 (-100.9644, -61.9879) -> (-99.9644, -60.9879)
  line L71 (-100.9644, 68.0121) -> (-99.9644, 67.0121)
  circle C1 centre (-24.4644, 61.5121) radius 1.7
  circle C2 centre (-93.9644, 54.5121) radius 1.7
  circle C3 centre (-87.4644, -55.4879) radius 1.7
  circle C4 centre (-17.4644, -48.4879) radius 1.7
  circle C5 centre (-24.4644, -55.4879) radius 1.7
  circle C6 centre (-93.9644, -48.4879) radius 1.7
  circle C7 centre (-87.4644, 61.5121) radius 1.7
  circle C8 centre (-17.4644, 54.5121) radius 1.7
  point P69 (-100.9644, 68.0121)
  point P74 (-100.9644, 68.0121)
  point P68 (-100.9644, -61.9879)
  point P75 (-100.9644, -61.9879)
  point P82 (-100.9644, 67.9414)
  point P83 (-100.9644, -61.9172)
  point P90 (-100.9644, -61.9879)
  point P91 (-100.9644, 68.0121)
  point P77 (-100.0144, -52.9379)
  point P80 (-100.0144, 58.9621)
  coincident P69 P74
  coincident P68 P75
  coincident L47 P82
  coincident L51 P83
  coincident P68 P90
  parallel L58 L70
  coincident P69 P91
  dimension "d147_3" distance L57 L63 = 0.95 (= "side_wall_thick1")
  dimension "d148_3" distance L57 L61 = 1.95 (= "side_wall_thick2")
  dimension "d151_3" distance L57 L59 = 0.95 (= "side_wall_thick1")
  dimension "d157_3" distance L64 L71 = 0.05 (= "wall_clearance")
  dimension "d158_3" distance L58 L70 = 0.05 (= "wall_clearance")
  dimension "wall_rorner_angle_3" angle L46 L71 = 45
  dimension "d165_3" angle L52 L70 = 45 (= "wall_rorner_angle_3")
  dimension "d170_3" distance P75 P77 = 9.05
  dimension "d175_3" distance P74 P80 = 9.05 (= "side_wall_col_length")
extrude "Extrude1" new body sketch "wall_base" profile of L47 L48 L50 L51 L57 L58 L59 L62 L61 L60 L63 L64 blind 69.9 (= "column_height - ( 2 * wall_clearance )") named "d128_3" from offset 0.05 (= "wall_clearance") named "d127_3" bodies "side cover"
sketch "Sketch3" plane through (100.9644, 0, 0) normal (1, 0, 0) x axis (0, 1, 0)
  line L1 (61.9172, 5.05) -> (-67.9414, 5.05)
  line L2 (61.9172, 74.95) -> (61.9172, 5.05)
  line L3 (-67.9414, 74.95) -> (61.9172, 74.95)
  line L4 (-67.9414, 5.05) -> (-67.9414, 74.95)
  line L5 (61.9172, 74.95) -> (-67.9414, 74.95)
  line L6 (61.9172, 74.95) -> (61.9172, 5.05)
  line L7 (61.9172, 5.05) -> (-67.9414, 5.05)
  line L8 (-67.9414, 74.95) -> (-67.9414, 5.05)
  line L9 (-57.9414, 64.95) -> (51.9172, 64.95)
  line L10 (-57.9414, 15.05) -> (-57.9414, 64.95)
  line L11 (51.9172, 15.05) -> (-57.9414, 15.05)
  line L12 (51.9172, 64.95) -> (51.9172, 15.05)
  circle C1 centre (-62.995, 60) radius 1.7
  circle C2 centre (-62.995, 20) radius 1.7
  circle C3 centre (56.9879, 60) radius 1.7
  circle C4 centre (56.9879, 20) radius 1.7
hole "Hole1" HoleDepth 4 named "d134_2" HoleDiameter 3.4 named "d135_2" TipAngle 118 named "d136_2"
sketch "Side locks" plane through (100.9644, 0, 0) normal (1, 0, 0) x axis (0, 1, 0)
  line L1 (61.9172, 74.95) -> (61.9172, 5.05)
  line L2 (-67.9414, 74.95) -> (61.9172, 74.95)
  line L3 (-67.9414, 5.05) -> (-67.9414, 74.95)
  line L4 (61.9172, 5.05) -> (-67.9414, 5.05)
  line L5 (-3.0121, 22.271) -> (-3.0121, 127.629)
  line L6 (25.9775, 40) -> (-161.8603, 40)
  line L7 (-67.9414, 64.95) -> (-67.9414, 74.95)
  line L8 (-61.9414, 74.95) -> (-67.9414, 74.95)
  line L9 (-61.9414, 59.95) -> (-61.9414, 74.95)
  line L10 (-67.9414, 64.95) -> (-61.9414, 59.95)
  line L11 (-67.9471, 64.9636) -> (-73.8914, 60.0101)
  line L12 (-73.8914, 60.0101) -> (-73.8914, 74.9101)
  line L13 (-67.9414, 64.9636) -> (-67.9471, 64.9636)
  line L14 (-67.9414, 74.9101) -> (-73.8914, 74.9101)
  line L15 (-67.9414, 5.0899) -> (-73.8914, 5.0899)
  line L16 (-73.8914, 19.9899) -> (-73.8914, 5.0899)
  line L17 (-67.9471, 15.0364) -> (-73.8914, 19.9899)
  line L18 (-67.9414, 15.0364) -> (-67.9471, 15.0364)
  line L19 (-67.9414, 15.05) -> (-67.9414, 5.05)
  line L20 (-61.9414, 5.05) -> (-67.9414, 5.05)
  line L21 (-61.9414, 20.05) -> (-61.9414, 5.05)
  line L22 (-67.9414, 15.05) -> (-61.9414, 20.05)
  line L23 (61.9172, 64.95) -> (61.9172, 74.95)
  line L24 (55.9172, 74.95) -> (61.9172, 74.95)
  line L25 (55.9172, 59.95) -> (55.9172, 74.95)
  line L26 (61.9172, 64.95) -> (55.9172, 59.95)
  line L27 (61.9172, 74.9101) -> (67.8672, 74.9101)
  line L28 (67.8672, 60.0101) -> (67.8672, 74.9101)
  line L29 (61.9172, 64.9636) -> (61.9229, 64.9636)
  line L30 (61.9229, 64.9636) -> (67.8672, 60.0101)
  line L31 (61.9172, 5.0899) -> (67.8672, 5.0899)
  line L32 (67.8672, 19.9899) -> (67.8672, 5.0899)
  line L33 (61.9172, 15.0364) -> (61.9229, 15.0364)
  line L34 (61.9229, 15.0364) -> (67.8672, 19.9899)
  line L35 (61.9172, 15.05) -> (61.9172, 5.05)
  line L36 (55.9172, 5.05) -> (61.9172, 5.05)
  line L37 (55.9172, 20.05) -> (55.9172, 5.05)
  line L38 (61.9172, 15.05) -> (55.9172, 20.05)
  point P17 (-67.9414, 64.9636)
  point P18 (-67.9414, 74.9101)
  point P10 (-67.9414, 74.95)
  point P24 (-67.9414, 5.05)
  point P11 (-67.9414, 64.95)
  point P25 (-67.9414, 15.05)
  point P12 (-61.9414, 74.95)
  point P26 (-61.9414, 5.05)
  point P13 (-61.9414, 59.95)
  point P27 (-61.9414, 20.05)
  point P14 (-67.9471, 64.9636)
  point P22 (-67.9471, 15.0364)
  point P15 (-73.8914, 60.0101)
  point P21 (-73.8914, 19.9899)
  point P16 (-73.8914, 74.9101)
  point P19 (-73.8914, 5.0899)
  point P23 (-67.9414, 15.0364)
  point P20 (-67.9414, 5.0899)
  point P28 (61.9172, 74.95)
  point P29 (61.9172, 64.95)
  point P30 (55.9172, 74.95)
  point P31 (55.9172, 59.95)
  point P35 (61.9229, 64.9636)
  point P34 (67.8672, 60.0101)
  point P32 (67.8672, 74.9101)
  point P36 (61.9172, 64.9636)
  point P33 (61.9172, 74.9101)
  point P37 (67.8672, 5.0899)
  point P38 (61.9172, 5.0899)
  point P39 (67.8672, 19.9899)
  point P40 (61.9229, 15.0364)
  point P41 (61.9172, 15.0364)
  point P42 (61.9172, 5.05)
  point P43 (61.9172, 15.05)
  point P44 (55.9172, 5.05)
  point P45 (55.9172, 20.05)
  vertical L5
  perpendicular L1 L6
  coincident L7 P17
  horizontal L14
  coincident L3 P18
  symmetric L6 P10 P24
  symmetric L6 P11 P25
  symmetric L6 P12 P26
  symmetric L6 P13 P27
  symmetric L6 P14 P22
  symmetric L6 P15 P21
  symmetric L6 P16 P19
  symmetric L6 P17 P23
  symmetric L6 P18 P20
  midpoint L2 L5
  midpoint L3 L6
  symmetric L5 P10 P28
  symmetric L5 P11 P29
  symmetric L5 P12 P30
  symmetric L5 P13 P31
  symmetric L5 P14 P35
  symmetric L5 P15 P34
  symmetric L5 P16 P32
  symmetric L5 P17 P36
  symmetric L5 P18 P33
  symmetric L5 P19 P37
  symmetric L5 P20 P38
  symmetric L5 P21 P39
  symmetric L5 P22 P40
  symmetric L5 P23 P41
  symmetric L5 P24 P42
  symmetric L5 P25 P43
  symmetric L5 P26 P44
  symmetric L5 P27 P45
  dimension "d315_3" distance P12 P13 = 15 (= "join_width2")
  dimension "d316_3" distance P10 P11 = 10 (= "join_width1")
  dimension "d317_3" distance P10 P12 = 6 (= "join_depth * 2")
  dimension "d320_3" distance P16 P18 = 5.95 (= "join_depth * 2 - wall_clearance")
  dimension "d321_3" distance P15 P16 = 14.9 (= "join_width2 - 2 * wall_clearance")
position "Position11"
extrude "Extrude3" add sketch "Side locks" profile of L2 L3 L4 L7 L8 L9 L10 L12 L11 L13 L14 L15 L16 L17 L18 L19 L20 L21 L22 against normal blind 0.95 (magnitude of "-side_wall_thick1")
sketch "Sketch3" plane through (0, 61.9879, 0) normal (0, 1, 0) x axis (-1, 0, 0)
  line L1 (-11.0351, 5.05) -> (-100.8937, 5.05)
  line L2 (-11.0351, 74.95) -> (-11.0351, 5.05)
  line L3 (-100.8937, 74.95) -> (-11.0351, 74.95)
  line L4 (-100.8937, 5.05) -> (-100.8937, 74.95)
  line L5 (-55.9644, -6.6527) -> (-55.9644, 156.5527)
  line L6 (83.5909, 40) -> (-105.6612, 40)
  line L7 (-100.8937, 64.95) -> (-100.8937, 74.95)
  line L8 (-94.8937, 74.95) -> (-100.8937, 74.95)
  line L9 (-94.8937, 59.95) -> (-94.8937, 74.95)
  line L10 (-100.8937, 64.95) -> (-94.8937, 59.95)
  line L11 (-100.9437, 64.9735) -> (-106.8437, 60)
  line L12 (-106.8437, 60) -> (-106.8437, 74.9)
  line L13 (-100.8937, 64.9735) -> (-100.9437, 64.9735)
  line L14 (-100.8937, 74.9) -> (-106.8437, 74.9)
  line L15 (-100.8937, 5.1) -> (-106.8437, 5.1)
  line L16 (-106.8437, 20) -> (-106.8437, 5.1)
  line L17 (-100.9437, 15.0265) -> (-106.8437, 20)
  line L18 (-100.8937, 15.0265) -> (-100.9437, 15.0265)
  line L19 (-100.8937, 15.05) -> (-100.8937, 5.05)
  line L20 (-94.8937, 5.05) -> (-100.8937, 5.05)
  line L21 (-94.8937, 20.05) -> (-94.8937, 5.05)
  line L22 (-100.8937, 15.05) -> (-94.8937, 20.05)
  line L23 (-11.0351, 5.1) -> (-5.0851, 5.1)
  line L24 (-5.0851, 20) -> (-5.0851, 5.1)
  line L25 (-10.9851, 15.0265) -> (-5.0851, 20)
  line L26 (-11.0351, 15.0265) -> (-10.9851, 15.0265)
  line L27 (-11.0351, 15.05) -> (-11.0351, 5.05)
  line L28 (-17.0351, 5.05) -> (-11.0351, 5.05)
  line L29 (-17.0351, 20.05) -> (-17.0351, 5.05)
  line L30 (-11.0351, 15.05) -> (-17.0351, 20.05)
  line L31 (-11.0351, 74.9) -> (-5.0851, 74.9)
  line L32 (-5.0851, 60) -> (-5.0851, 74.9)
  line L33 (-11.0351, 64.9735) -> (-10.9851, 64.9735)
  line L34 (-10.9851, 64.9735) -> (-5.0851, 60)
  line L35 (-11.0351, 64.95) -> (-11.0351, 74.95)
  line L36 (-17.0351, 74.95) -> (-11.0351, 74.95)
  line L37 (-17.0351, 59.95) -> (-17.0351, 74.95)
  line L38 (-11.0351, 64.95) -> (-17.0351, 59.95)
  point P17 (-100.8937, 64.9735)
  point P18 (-100.8937, 74.9)
  point P10 (-100.8937, 74.95)
  point P24 (-100.8937, 5.05)
  point P11 (-100.8937, 64.95)
  point P25 (-100.8937, 15.05)
  point P12 (-94.8937, 74.95)
  point P26 (-94.8937, 5.05)
  point P13 (-94.8937, 59.95)
  point P27 (-94.8937, 20.05)
  point P14 (-100.9437, 64.9735)
  point P22 (-100.9437, 15.0265)
  point P15 (-106.8437, 60)
  point P21 (-106.8437, 20)
  point P16 (-106.8437, 74.9)
  point P19 (-106.8437, 5.1)
  point P23 (-100.8937, 15.0265)
  point P20 (-100.8937, 5.1)
  point P42 (-11.0351, 74.95)
  point P43 (-11.0351, 64.95)
  point P44 (-17.0351, 74.95)
  point P45 (-17.0351, 59.95)
  point P40 (-10.9851, 64.9735)
  point P39 (-5.0851, 60)
  point P37 (-5.0851, 74.9)
  point P41 (-11.0351, 64.9735)
  point P38 (-11.0351, 74.9)
  point P28 (-5.0851, 5.1)
  point P29 (-11.0351, 5.1)
  point P30 (-5.0851, 20)
  point P31 (-10.9851, 15.0265)
  point P32 (-11.0351, 15.0265)
  point P33 (-11.0351, 5.05)
  point P34 (-11.0351, 15.05)
  point P35 (-17.0351, 5.05)
  point P36 (-17.0351, 20.05)
  vertical L5
  horizontal L6
  midpoint L3 L5
  midpoint L2 L6
  coincident L7 P17
  coincident L4 P17
  perpendicular L7 L14
  coincident L4 P18
  symmetric L6 P10 P24
  symmetric L6 P11 P25
  symmetric L6 P12 P26
  symmetric L6 P13 P27
  symmetric L6 P14 P22
  symmetric L6 P15 P21
  symmetric L6 P16 P19
  symmetric L6 P17 P23
  symmetric L6 P18 P20
  symmetric L5 P10 P42
  symmetric L5 P11 P43
  symmetric L5 P12 P44
  symmetric L5 P13 P45
  symmetric L5 P14 P40
  symmetric L5 P15 P39
  symmetric L5 P16 P37
  symmetric L5 P17 P41
  symmetric L5 P18 P38
  symmetric L5 P19 P28
  symmetric L5 P20 P29
  symmetric L5 P21 P30
  symmetric L5 P22 P31
  symmetric L5 P23 P32
  symmetric L5 P24 P33
  symmetric L5 P25 P34
  symmetric L5 P26 P35
  symmetric L5 P27 P36
  dimension "d332" distance P12 P13 = 15 (= "join_width2")
  dimension "d333" distance P10 P12 = 6 (= "join_depth * 2")
  dimension "d334" distance P10 P11 = 10 (= "join_width1")
  dimension "d336" distance P15 P16 = 14.9 (= "join_width2 - ( 2 * wall_clearance )")
  dimension "d337" distance P16 P18 = 5.95 (= "join_depth * 2 - wall_clearance")
  dimension "d338" distance P14 P17 = 0.05 (= "wall_clearance")
sketch "Sketch1" plane through (0, 0, 5) normal (0, 0, 1) x axis (-1, 0, 0)
  line L1 (-98.9644, -53.9879) -> (-98.9644, -59.9879)
  line L2 (-92.9644, -53.9879) -> (-98.9644, -53.9879)
  line L3 (-92.9644, -59.9879) -> (-92.9644, -53.9879)
  line L4 (-98.9644, -59.9879) -> (-92.9644, -59.9879)
  line L5 (-12.9644, 60.0121) -> (-12.9644, 66.0121)
  line L6 (-18.9644, 60.0121) -> (-12.9644, 60.0121)
  line L7 (-18.9644, 66.0121) -> (-18.9644, 60.0121)
  line L8 (-12.9644, 66.0121) -> (-18.9644, 66.0121)
  line L9 (-45.9644, -51.9879) -> (-20.9644, -51.9879)
  line L10 (-40.9644, -54.9879) -> (-45.9644, -51.9879)
  line L11 (-70.9644, -54.9879) -> (-40.9644, -54.9879)
  line L12 (-65.9644, -51.9879) -> (-70.9644, -54.9879)
  line L13 (-90.9644, -51.9879) -> (-65.9644, -51.9879)
  line L14 (-90.9644, -6.9879) -> (-90.9644, -51.9879)
  line L15 (-93.9644, -11.9879) -> (-90.9644, -6.9879)
  line L16 (-93.9644, 18.0121) -> (-93.9644, -11.9879)
  line L17 (-90.9644, 13.0121) -> (-93.9644, 18.0121)
  line L18 (-90.9644, 58.0121) -> (-90.9644, 13.0121)
  line L19 (-65.9644, 58.0121) -> (-90.9644, 58.0121)
  line L20 (-70.9644, 61.0121) -> (-65.9644, 58.0121)
  line L21 (-40.9644, 61.0121) -> (-70.9644, 61.0121)
  line L22 (-45.9644, 58.0121) -> (-40.9644, 61.0121)
  line L23 (-20.9644, 58.0121) -> (-45.9644, 58.0121)
  line L24 (-20.9644, 13.0121) -> (-20.9644, 58.0121)
  line L25 (-17.9644, 18.0121) -> (-20.9644, 13.0121)
  line L26 (-17.9644, -11.9879) -> (-17.9644, 18.0121)
  line L27 (-20.9644, -6.9879) -> (-17.9644, -11.9879)
  line L28 (-20.9644, -51.9879) -> (-20.9644, -6.9879)
  line L29 (-12.9644, -53.9879) -> (-18.9644, -53.9879)
  line L30 (-12.9644, -59.9879) -> (-12.9644, -53.9879)
  line L31 (-18.9644, -59.9879) -> (-12.9644, -59.9879)
  line L32 (-18.9644, -53.9879) -> (-18.9644, -59.9879)
  line L33 (-98.9644, 60.0121) -> (-92.9644, 60.0121)
  line L34 (-98.9644, 66.0121) -> (-98.9644, 60.0121)
  line L35 (-92.9644, 66.0121) -> (-98.9644, 66.0121)
  line L36 (-92.9644, 60.0121) -> (-92.9644, 66.0121)
  line L37 (-10.9644, -6.9879) -> (-10.9644, -61.9879)
  line L38 (-13.9644, -11.9879) -> (-10.9644, -6.9879)
  line L39 (-13.9644, 18.0121) -> (-13.9644, -11.9879)
  line L40 (-10.9644, 13.0121) -> (-13.9644, 18.0121)
  line L41 (-10.9644, 68.0121) -> (-10.9644, 13.0121)
  line L42 (-45.9644, 68.0121) -> (-10.9644, 68.0121)
  line L43 (-40.9644, 65.0121) -> (-45.9644, 68.0121)
  line L44 (-70.9644, 65.0121) -> (-40.9644, 65.0121)
  line L45 (-65.9644, 68.0121) -> (-70.9644, 65.0121)
  line L46 (-100.9644, 68.0121) -> (-65.9644, 68.0121)
  line L47 (-100.9644, 13.0121) -> (-100.9644, 68.0121)
  line L48 (-97.9644, 18.0121) -> (-100.9644, 13.0121)
  line L49 (-97.9644, -11.9879) -> (-97.9644, 18.0121)
  line L50 (-100.9644, -6.9879) -> (-97.9644, -11.9879)
  line L51 (-100.9644, -61.9879) -> (-100.9644, -6.9879)
  line L52 (-65.9644, -61.9879) -> (-100.9644, -61.9879)
  line L53 (-70.9644, -58.9879) -> (-65.9644, -61.9879)
  line L54 (-40.9644, -58.9879) -> (-70.9644, -58.9879)
  line L55 (-45.9644, -61.9879) -> (-40.9644, -58.9879)
  line L56 (-10.9644, -61.9879) -> (-45.9644, -61.9879)
  line L57 (-100.9644, -61.9879) -> (-10.9644, -61.9879)
  line L58 (-99.9644, -60.9879) -> (-100.9644, -61.9879)
  line L59 (-91.9644, -60.9879) -> (-99.9644, -60.9879)
  line L60 (-91.9644, -59.9879) -> (-91.9644, -60.9879)
  line L61 (-19.9644, -59.9879) -> (-91.9644, -59.9879)
  line L62 (-19.9644, -60.9879) -> (-19.9644, -59.9879)
  line L63 (-11.9644, -60.9879) -> (-19.9644, -60.9879)
  line L64 (-10.9644, -61.9879) -> (-11.9644, -60.9879)
  line L65 (-99.9437, -61.0379) -> (-100.8937, -61.9879)
  line L66 (-91.9144, -61.0379) -> (-99.9437, -61.0379)
  line L67 (-91.9144, -60.0379) -> (-91.9144, -61.0379)
  line L68 (-20.0144, -60.0379) -> (-91.9144, -60.0379)
  line L69 (-20.0144, -61.0379) -> (-20.0144, -60.0379)
  line L70 (-11.9851, -61.0379) -> (-20.0144, -61.0379)
  line L71 (-11.0351, -61.9879) -> (-11.9851, -61.0379)
  circle C1 centre (-24.4644, 61.5121) radius 1.7
  circle C2 centre (-93.9644, 54.5121) radius 1.7
  circle C3 centre (-87.4644, -55.4879) radius 1.7
  circle C4 centre (-17.4644, -48.4879) radius 1.7
  circle C5 centre (-24.4644, -55.4879) radius 1.7
  circle C6 centre (-93.9644, -48.4879) radius 1.7
  circle C7 centre (-87.4644, 61.5121) radius 1.7
  circle C8 centre (-17.4644, 54.5121) radius 1.7
  point P46 (-10.9644, -61.9879)
  point P74 (-10.9644, -61.9879)
  point P61 (-100.9644, -61.9879)
  point P76 (-100.9644, -61.9879)
  point P68 (-99.9644, -60.9879)
  point P77 (-99.9644, -60.9879)
  point P69 (-91.9644, -60.9879)
  point P78 (-91.9644, -60.9879)
  point P70 (-91.9644, -59.9879)
  point P79 (-91.9644, -59.9879)
  point P71 (-19.9644, -59.9879)
  point P80 (-19.9644, -59.9879)
  point P72 (-19.9644, -60.9879)
  point P81 (-19.9644, -60.9879)
  point P73 (-11.9644, -60.9879)
  point P82 (-11.9644, -60.9879)
  point P89 (-11.0351, -61.9879)
  point P90 (-100.8937, -61.9879)
  point P75 (-100.9644, -61.9879)
  coincident P46 P74
  coincident P61 P76
  coincident P68 P77
  coincident P69 P78
  coincident P70 P79
  coincident P71 P80
  coincident P72 P81
  coincident P73 P82
  coincident L56 P89
  coincident L52 P90
  dimension "d228_1" distance L57 L70 = 0.95 (= "side_wall_thick1")
  dimension "d229_1" distance L57 L68 = 1.95 (= "side_wall_thick2")
  dimension "d230_1" distance L57 L66 = 0.95 (= "side_wall_thick1")
  dimension "d231_1" distance P74 P75 = 90 (= "plate_height")
  dimension "d232_1" distance L64 L71 = 0.05 (= "wall_clearance")
  dimension "d233_1" distance L58 L65 = 0.05 (= "wall_clearance")
  dimension "d234_1" angle L57 L58 = 45 (= "wall_rorner_angle")
  dimension "d235_1" distance P74 L69 = 9.05 (= "side_wall_col_length")
  dimension "d244_1" distance P75 L67 = 9.05 (= "side_wall_col_length")
extrude "Extrude1" new body sketch "Sketch1" profile of L52 L53 L55 L56 blind 69.9 (= "column_height - ( 2 * wall_clearance )") named "d217_1" from offset 0.05 (= "wall_clearance") named "d216_1"
sketch "Sketch2" plane through (0, 61.9879, 0) normal (0, 1, 0) x axis (-1, 0, 0)
  line L1 (-11.0351, 74.95) -> (-100.8937, 74.95)
  line L2 (-100.8937, 74.95) -> (-100.8937, 5.05)
  line L3 (-11.0351, 74.95) -> (-11.0351, 5.05)
  line L4 (-11.0351, 5.05) -> (-100.8937, 5.05)
  line L5 (-11.0351, 74.95) -> (-11.0351, 5.05)
  line L6 (-100.8937, 74.95) -> (-11.0351, 74.95)
  line L7 (-100.8937, 5.05) -> (-100.8937, 74.95)
  line L8 (-90.8937, 64.95) -> (-21.0351, 64.95)
  line L9 (-90.8937, 15.05) -> (-90.8937, 64.95)
  line L10 (-21.0351, 15.05) -> (-90.8937, 15.05)
  line L11 (-21.0351, 64.95) -> (-21.0351, 15.05)
  circle C1 centre (-95.9644, 60) radius 1.7
  circle C2 centre (-95.9644, 20) radius 1.7
  circle C3 centre (-15.9644, 20) radius 1.7
  circle C4 centre (-15.9644, 60) radius 1.7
